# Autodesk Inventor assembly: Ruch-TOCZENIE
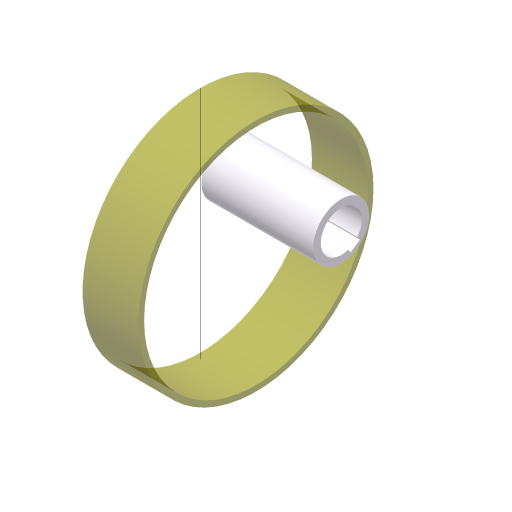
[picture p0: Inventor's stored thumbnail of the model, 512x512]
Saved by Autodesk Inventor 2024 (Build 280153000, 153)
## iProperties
Created: 2023-03
Part Number: Ruch-TOCZENIE
Document SubType Name: Assembly
Designer: Andrzej Jaskulski
Manufacturer: Standard
Standards Organization: Custom
Stock Number: Ruch-TOCZENIE
Checked By: A.J.
Engr Approved By: Andrzej Jaskulski
Mfg Approved By: Andrzej Jaskulski
Authority: A.J.
Company: ATC
Title: A.J.: Kurs R2024-MEP
Author: Andrzej Jaskulski
Revision Number: 1/24
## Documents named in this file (3)
- C:\Users\AndJas\Documents\R2024-MEP\Obszar roboczy\Ruch-TOCZENIE.iam
- C:\Users\AndJas\Documents\R2024-MEP\Obszar roboczy\Ruch-TOCZENIE-Bieżnia.ipt
- C:\Users\AndJas\Documents\R2024-MEP\Obszar roboczy\Ruch-TOCZENIE-Rolka.ipt
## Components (2 placed, 2 different names)
1. Ruch-TOCZENIE-Bieżnia:1 — Równoległość-CZÓŁ, Warunek początkowy 1, Warunek początkowy 2
2. Ruch-TOCZENIE-Rolka:1 — Równoległość-CZÓŁ, Warunek początkowy 1, Warunek początkowy 2
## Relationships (3: Flush 1, Mate 1, Angle 1)
- Równoległość-CZÓŁ [Flush]: Ruch-TOCZENIE-Bieżnia:1 ↔ Ruch-TOCZENIE-Rolka:1
- Warunek początkowy 1 [Mate]: Ruch-TOCZENIE-Bieżnia:1 ↔ Ruch-TOCZENIE-Rolka:1
- Warunek początkowy 2 [Angle]: Ruch-TOCZENIE-Bieżnia:1 ↔ Ruch-TOCZENIE-Rolka:1
## Named parameters: DE = 15 mm
